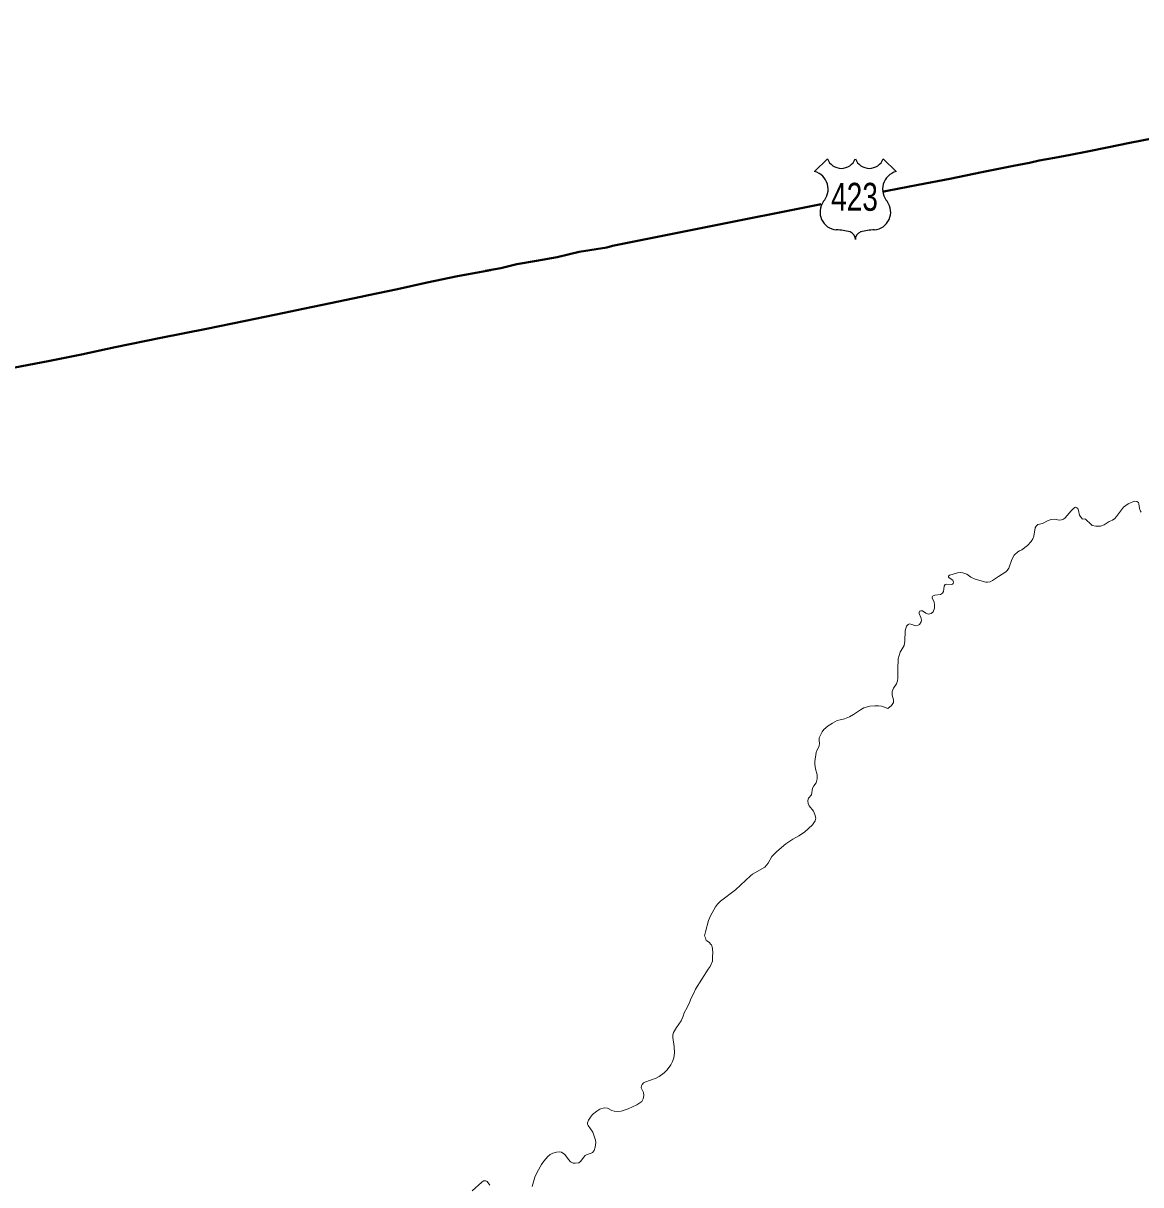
# Model space of a CAD drawing. Extents: x 553962 to 842807, y 8883888 to 9032388.
# Drawn here: x 587242 to 590040, y 8912077 to 8914985 of the extents above; entities that cross this region are included whole.
import ezdxf
from ezdxf.enums import TextEntityAlignment as Align

# ---------------------------------------------------------------- set-up
doc = ezdxf.new("R2010")
doc.units = 0
doc.header["$LTSCALE"] = 200
doc.layers.add('6', color=7, linetype='Continuous', lineweight=13)

msp = doc.modelspace()

# ---------------------------------------------------------------- linework, layer by layer
at = {"layer": '6', "lineweight": 25}
for p, q in [((589223.6, 8914613.8), (589255.6, 8914645.8)), ((589395.4, 8914645.8), (589427.4, 8914613.8))]:
    msp.add_line(p, q, dxfattribs=at)
at = {"layer": '6', "lineweight": 40}
for points in [[(590967.2, 8914985.2), (590878.4, 8914955.6), (590794.3, 8914928.8), (590714.1, 8914902.8), (590638.7, 8914877.7), (590563.6, 8914852.3), (590490.5, 8914828.4), (590417.3, 8914804.2), (590344.2, 8914780.3), (590271, 8914756.5), (590202.2, 8914734.8), (590164.9, 8914722.1), (590133.8, 8914713.2), (590073.3, 8914697.5), (590013.2, 8914685.6), (589955.9, 8914674.1), (589907.1, 8914664.4), (589864, 8914655.5), (589824, 8914648.4), (589785.5, 8914641.2), (589761.6, 8914635.9), (589721.8, 8914628.2)], [(589721.8, 8914628.2), (589642.1, 8914611.9), (589562.3, 8914595.5), (589483.2, 8914580.8), (589404.8, 8914565.2), (589393.5, 8914562.8)], [(589240.3, 8914531.9), (589219.4, 8914527.9), (588967.4, 8914478), (588717.5, 8914427.5), (588703.5, 8914423.5), (588633.7, 8914412.4), (588579.1, 8914399.7), (588527.3, 8914390), (588477.7, 8914381.7), (588437.3, 8914372.2), (588399.5, 8914364.9)], [(588411.7, 8914367.2), (588329.2, 8914351.8), (588253.3, 8914335.7), (588178.5, 8914319.1), (588105.9, 8914304.4), (588087.3, 8914299.9)], [(588087.3, 8914299.9), (587991.2, 8914280), (587942.9, 8914269.9)], [(587942.9, 8914269.9), (587894.7, 8914259.8), (587797.8, 8914239.6), (587700.8, 8914220), (587586.4, 8914197.2), (587471.4, 8914174.2), (587387.3, 8914155.4), (587304, 8914139.1), (587220.7, 8914122.7), (587137.7, 8914106.3), (587056.1, 8914089), (587006.5, 8914079.3)]]:
    msp.add_lwpolyline(points, dxfattribs=at)
at = {"layer": '6'}
for points in [[(589979.2, 8913749.7), (589979.2, 8913749.7), (589975.1, 8913745.1), (589969.6, 8913740.7), (589960.9, 8913737.1), (589948.4, 8913729.2), (589939.2, 8913725.8), (589927.6, 8913725.4), (589918.8, 8913727.8), (589915.8, 8913729.6), (589902.3, 8913743.6), (589900.3, 8913744.2), (589895.6, 8913743.2), (589893.3, 8913744.2), (589887.2, 8913753.2), (589884.3, 8913764.8), (589882.3, 8913769.8), (589880.3, 8913771.8), (589877, 8913773), (589873.1, 8913771.2), (589865.8, 8913764.5), (589850.8, 8913746.3), (589846.8, 8913743.5), (589841.7, 8913741.9), (589836, 8913741.1), (589823.9, 8913743.2), (589816.2, 8913742.8), (589808.7, 8913740.2), (589794.3, 8913732.8), (589782.7, 8913729.6), (589778.4, 8913725.8), (589776, 8913721.3), (589772.3, 8913700.5), (589769.6, 8913694.1), (589765.7, 8913687.5), (589757, 8913677.6), (589742.1, 8913666.2), (589736.6, 8913664.2), (589732.6, 8913661.8), (589723.6, 8913652.9), (589717.2, 8913642.7), (589709.6, 8913620.5), (589705.8, 8913614.7), (589702.7, 8913611.7), (589683.9, 8913599.8), (589669.4, 8913589.6), (589663.5, 8913586.8), (589656.5, 8913585.3), (589652.4, 8913585.5), (589625.6, 8913592.9), (589615.1, 8913598.1), (589604.5, 8913605.5), (589594.8, 8913609.3), (589588.7, 8913609.9), (589581.5, 8913609.2), (589568.2, 8913604.4), (589561.1, 8913602.8), (589558.6, 8913600.4), (589559.1, 8913598), (589560.4, 8913596.6), (589570, 8913590.6), (589571, 8913585.4), (589570.1, 8913582.2), (589568.5, 8913580.6), (589566.4, 8913580), (589554.3, 8913580.6), (589550.8, 8913579.8), (589548.3, 8913575.2), (589546.7, 8913562.5), (589543.5, 8913558.1), (589538.4, 8913554.9), (589524.5, 8913552.9), (589519, 8913550.7), (589517.5, 8913549.1), (589517.5, 8913546.1), (589523, 8913535.2), (589524, 8913529), (589523.7, 8913520.8), (589520.5, 8913511.4), (589515.2, 8913507.2), (589508.7, 8913505.4), (589501.8, 8913507.6), (589493.6, 8913513.4), (589489.8, 8913513.8), (589486.5, 8913512.9), (589485.4, 8913511.3), (589485.5, 8913507.3), (589489.8, 8913497.1), (589490.8, 8913490.3), (589490, 8913486.3), (589486.4, 8913479.7), (589482.6, 8913477.5), (589477, 8913476.1), (589467.2, 8913479.9), (589460.9, 8913481.3), (589457.6, 8913479.4), (589453.3, 8913475), (589450.1, 8913463.6), (589449.3, 8913437.6), (589447.7, 8913427.2), (589437.8, 8913409.9)], [(590041, 8913761), (590039.3, 8913763.4), (590037.5, 8913770.2), (590035.8, 8913782), (590034.6, 8913785.2), (590030.5, 8913787.8), (590024.8, 8913788.6), (590009, 8913781.8), (589997.3, 8913773.4), (589989.2, 8913763.7), (589979.2, 8913749.7)], [(589437.8, 8913409.9), (589433.1, 8913393.5), (589433.1, 8913393.5), (589431.5, 8913367.8), (589432.1, 8913345.4), (589431.2, 8913338.2), (589428.5, 8913331.2), (589421, 8913319.9), (589417.5, 8913311.9), (589417.5, 8913302.5), (589420.9, 8913290.9), (589420.9, 8913284.3), (589416.4, 8913276.5), (589406.9, 8913269), (589396.3, 8913273)], [(589396.3, 8913273), (589390.8, 8913274.8), (589383.3, 8913276), (589373.9, 8913276), (589361.7, 8913275), (589346.8, 8913270.5), (589338, 8913265.9), (589320.9, 8913254.3), (589310.8, 8913248.6), (589298.3, 8913243.4), (589287.1, 8913241.2), (589280.3, 8913239), (589268.3, 8913232.8), (589257.4, 8913225.7), (589246.9, 8913216.7), (589242.3, 8913210.5), (589235.2, 8913196), (589234.8, 8913187.8)], [(589234.8, 8913187.8), (589236.1, 8913183.2), (589235.3, 8913175), (589229.7, 8913165.4), (589227.3, 8913159.4), (589224.2, 8913136.7), (589224.2, 8913129.5), (589225.4, 8913118.3), (589229.5, 8913102.9), (589230.1, 8913092.7), (589227.2, 8913082.8), (589221.5, 8913075.8), (589218.6, 8913070), (589215.3, 8913053.2), (589208.5, 8913045), (589207.2, 8913041.9), (589206.6, 8913037.8), (589207.5, 8913031.5), (589209.8, 8913025.7), (589220.4, 8913011.7), (589224.2, 8913003.7), (589226.6, 8912994.5), (589225.1, 8912987.7)], [(589225.1, 8912987.7), (589225.1, 8912987.7), (589217.9, 8912977.7), (589198, 8912959.6), (589184.3, 8912950.4), (589169.3, 8912941.7), (589151.8, 8912930.3), (589128.6, 8912911.4), (589116.4, 8912898.2), (589106.9, 8912881.9), (589099, 8912871.9), (589068.3, 8912854), (589062.8, 8912850), (589025, 8912815.3), (588987.8, 8912786.4), (588979.9, 8912778.8), (588975.2, 8912772.6), (588963.1, 8912750.1), (588957.9, 8912738.7), (588949.9, 8912709.8), (588948, 8912700.2), (588950.1, 8912694.8), (588951.6, 8912688.4), (588953.3, 8912687.2), (588960.2, 8912683), (588963, 8912678.7), (588965.1, 8912677), (588967.8, 8912668.8), (588968.2, 8912654.7), (588967.7, 8912650.4), (588967.8, 8912636.2), (588962.2, 8912622.8), (588956.7, 8912616.2), (588925.6, 8912566.2), (588921.1, 8912556.2), (588914.4, 8912544), (588910, 8912532.8), (588904.4, 8912520.6), (588896.9, 8912507.2), (588894.7, 8912498.6), (588888.9, 8912486.8), (588877.2, 8912470.3), (588870.5, 8912457.5), (588868.6, 8912451.7), (588868.1, 8912445.7), (588872, 8912422.7), (588872.3, 8912407.2), (588870.6, 8912394.4), (588867.9, 8912385), (588863.4, 8912376.8), (588854, 8912364.7), (588846.6, 8912357.1), (588834.5, 8912347.5), (588826.4, 8912343.3), (588798.1, 8912333.4), (588795.1, 8912331.6), (588791.9, 8912328), (588789.9, 8912324), (588789.2, 8912319.6), (588794.8, 8912308), (588795.9, 8912300.3), (588794.5, 8912291.7), (588790.7, 8912285.1), (588778.4, 8912277.1), (588756.6, 8912266.8)], [(588756.6, 8912266.8), (588738.9, 8912261), (588729, 8912260.2), (588721.3, 8912260.6), (588715.5, 8912262.2), (588704.7, 8912268.2), (588696.6, 8912269.5), (588685.5, 8912265.7), (588677.7, 8912261.1), (588667.4, 8912252.3), (588662.1, 8912246.2), (588656.9, 8912238.2), (588655.1, 8912231.8), (588655.1, 8912228.4), (588656.5, 8912225), (588667.9, 8912208.6), (588674.8, 8912188.2), (588675.3, 8912182.2), (588674.1, 8912170.3), (588671.1, 8912162.7), (588667.4, 8912157.3), (588664.2, 8912155.3), (588654.1, 8912152.3), (588649.2, 8912149.7), (588644.3, 8912144.9), (588637.8, 8912135.8), (588632.8, 8912131.8), (588624.2, 8912130.4), (588618.8, 8912131), (588612, 8912134), (588607, 8912139.8), (588597.9, 8912152.2), (588589.9, 8912158.2), (588585, 8912159.2), (588577.3, 8912158.2), (588568.1, 8912155.6), (588561.2, 8912152.3)], [(588561.2, 8912152.3), (588555.2, 8912147.5), (588555.2, 8912147.5), (588545.5, 8912135.7), (588539.6, 8912127.1), (588528.7, 8912108.2), (588522.9, 8912095.4), (588516.2, 8912072.3)], [(588410.3, 8912075.8), (588403.6, 8912084.6), (588400.1, 8912086.8), (588394.6, 8912086), (588390.3, 8912083.4), (588365.5, 8912061.7)]]:
    msp.add_lwpolyline(points, dxfattribs=at)
at = {"layer": '6', "lineweight": 25}
for centre, radius, start, end in [((589290.5, 8914659.2), 37.4, 200.9593, 339.0407), ((589360.5, 8914659.2), 37.4, 200.9593, 339.0407), ((589211.2, 8914569.5), 46.1, 317.5721, 74.3689), ((589439.8, 8914569.5), 46.1, 105.6277, 222.4279), ((589281.9, 8914512.4), 44.9, 144.7373, 264.6578), ((589369.1, 8914512.4), 44.9, 275.3422, 35.2627), ((589277.5, 8914349.7), 118, 72.8937, 89.9006), ((589306.6, 8914444.4), 18.9, 357.6934, 72.9296), ((589344.4, 8914444.4), 18.9, 107.0704, 182.3065), ((589373.5, 8914349.7), 118, 90.0994, 107.1063)]:
    msp.add_arc(centre, radius, start, end, dxfattribs=at)

# ---------------------------------------------------------------- texts
at = {"layer": '6', "width": 0.75}
msp.add_text('423', height=70, dxfattribs=at).set_placement((589323.4, 8914515.5), align=Align.CENTER)

doc.saveas('drawing.dxf')
